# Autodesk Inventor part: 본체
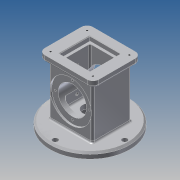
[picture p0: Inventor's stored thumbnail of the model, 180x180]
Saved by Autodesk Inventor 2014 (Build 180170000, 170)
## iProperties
Created: 2019-08
Part Number: 본체
Material: 알루미늄 6061
Document SubType Name: Modeling
Designer: kb542-14
Density: 2.71 g/cm^3
Appearance: 알루미늄 - 평지
Mass: 1040.33 g
Surface Area: 788.05 cm^2
Volume: 383.884 cm^3
Author: kb542-14
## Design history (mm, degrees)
sketch "스케치1"
  geometry: L1 (37, 33)-(-37, 33); L2 (-37, 33)-(-37, -33); L3 (-37, -33)-(37, -33); L4 (37, -33)-(37, 33); L5 (37, 33)-(-37, -33); L6 (-37, 33)-(37, -33); 1 further point
  constraints: 12 end point, 2 midpoint, 2 parallel, 1 horizontal, 1 perpendicular
  dimensions: "d1" = 74 distance of L1.start L1.end; "d2" = 66 distance of L1.end L2.end
extrude "돌출1" new body sketch "스케치1" distance "d3" = 88; taper "d4" = 0 deg
sketch "스케치2"
  geometry: L1 (46, 41)-(-46, 41); L2 (-46, 41)-(-46, -41); L3 (-46, -41)-(46, -41); L4 (46, -41)-(46, 41); L5 (46, 41)-(-46, -41); L6 (-46, 41)-(46, -41); 1 further point
  constraints: 12 end point, 2 midpoint, 2 parallel, 1 horizontal, 1 perpendicular
  dimensions: "d5" = 92 distance of L1.start L1.end; "d6" = 82 distance of L1.end L2.end
extrude "돌출2" join sketch "스케치2" distance "d7" = 10; taper "d8" = 0 deg
sketch "스케치3"
  geometry: C1 r 67.5 at (0, 0); 1 further point
  constraints: 1 centre point, 1 coincident
  dimensions: "d9" = 135 diameter of C1
extrude "돌출3" join sketch "스케치3" distance "d10" = 10; taper "d11" = 0 deg
sketch "스케치5"
  geometry: L1 (-33, 88)-(-41, 88) reference; L2 (-41, 88)-(-41, 98) reference; L3 (-41, 98)-(41, 98) reference; L4 (41, 98)-(41, 88) reference; L5 (41, 88)-(33, 88) reference; L6 (33, 88)-(33, 0) reference; L7 (33, 0)-(67.5, 0) reference; L8 (67.5, 0)-(67.5, -10) reference; L9 (67.5, -10)-(-67.5, -10) reference; L10 (-67.5, -10)-(-67.5, 0) reference; L11 (-67.5, 0)-(-33, 0) reference; L12 (-33, 0)-(-33, 88) reference; L13 (-33, 44)-(33, 44); L14 (-33, 79)-(-30, 79); L15 (-30, 79)-(-30, 68); L16 (-30, 68)-(30, 68); L17 (30, 68)-(30, 79); L18 (30, 79)-(33, 79); L19 (-33, 79)-(-33, 44); L20 (33, 79)-(33, 44); 1 further point
  constraints: 16 end point, 4 parallel, 2 collinear, 2 midpoint, 2 point on line, 1 perpendicular
  dimensions: "d18" = 70 diameter of L14 L13; "d20" = 48 diameter of L16 L13; "d21" = 70 diameter of L18 L13; "d22" = 3 distance of L14.start L14.end; "d23" = 3 distance of L17.end L18.end
revolve "회전2" sketch "스케치5" stored, may be unused: angle "d24" = 90 deg
sketch "스케치6"
  geometry: L1 (26, 26)-(-26, 26); L2 (-26, 26)-(-26, -26); L3 (-26, -26)-(26, -26); L4 (26, -26)-(26, 26); L5 (26, 26)-(-26, -26); L6 (-26, 26)-(26, -26); 1 further point
  constraints: 12 end point, 2 midpoint, 2 parallel, 1 horizontal, 1 perpendicular
  dimensions: "d25" = 52 distance of L1.end L2.end; "d26" = 52 distance of L1.start L1.end
extrude "돌출4" cut sketch "스케치6" distance "d27" = 8; taper "d28" = 0 deg
sketch "스케치7"
  geometry: L1 (22, 22)-(-22, 22); L2 (-22, 22)-(-22, -22); L3 (-22, -22)-(22, -22); L4 (22, -22)-(22, 22); L5 (22, 22)-(-22, -22); L6 (-22, 22)-(22, -22); 1 further point
  constraints: 12 end point, 2 midpoint, 2 parallel, 1 horizontal, 1 perpendicular
  dimensions: "d29" = 44 distance of L1.end L2.end; "d30" = 44 distance of L1.start L1.end
extrude "돌출5" cut sketch "스케치7" distance "d31" = 74; taper "d32" = 0 deg
sketch "스케치8"
  geometry: C1 r 67.5 at (0, 0) reference; C2 r 25 at (0, 0); C3 r 12.5 at (0, 0)
  constraints: 2 centre point, 2 coincident
  dimensions: "d34" = 50 diameter of C2; "d35" = 25 diameter of C3
extrude "돌출6" cut sketch "스케치8" distance "d36" = 50; taper "d37" = 0 deg
extrude "돌출7" cut sketch "스케치8" distance "d38" = 18; taper "d39" = 0 deg
sketch "스케치9"
  geometry: L1 (-88, 66)-(-88, 0) reference; L2 (-98, 100.5)-(-98, -34.5) reference; 5 further points
  constraints: 2 horizontal alignment, 2 midpoint
  dimensions: "d40" = 37 distance from line of L2 point (-61, 33); "d41" = 43 distance of point (-61, 33) point (-18, 33)
hole "구멍1" sketch "스케치9" at (-18, 33), (-61, 33) diameter "d42" = 4.917; stored, may be unused: countersink angle "d46" = 90 deg, drill point angle "d48" = 118 deg; dims "d43" = 6, "d44" = 4, "d45" = 2, "d47" = 22.75
fillet "모깎기1" dims "d49" = 3
fillet "모깎기2" dims "d50" = 3
fillet "모깎기3" dims "d51" = 3
fillet "모깎기4" dims "d52" = 10
fillet "모깎기6" dims "d54" = 3
fillet "모깎기7" dims "d55" = 3
fillet "모깎기8" dims "d56" = 3
chamfer "모따기1" distance "d57" = 3; stored, may be unused: second distance "d58" = 2, angle "d59" = 45 deg
fillet "모깎기9" dims "d60" = 3
sketch "스케치12"
  geometry: C1 r 64.5 at (0, 0) reference; C2 r 4.5 at (0, 59); C3 r 4.5 at (0, -59); C4 r 4.5 at (59, 0); A1 r 59 centre (0, 0) between (0, 59) and (0, -59)
  constraints: 4 centre point, 3 point on circle, 2 vertical alignment, 1 coincident, 1 horizontal alignment
  dimensions: "d61" = 118 diameter of A1; "d62" = 9 diameter of C2; "d63" = 9 diameter of C4; "d65" = 9 diameter of C3
extrude "돌출8" cut sketch "스케치12" stored distance "d66" = 18; taper "d67" = 0 deg
sketch "스케치13"
  geometry: A1 r 10 centre (36, -31) between (36, -41) and (46, -31) reference; A2 r 10 centre (36, 31) between (46, 31) and (36, 41) reference; A3 r 10 centre (-36, 31) between (-36, 41) and (-46, 31) reference; A4 r 10 centre (-36, -31) between (-46, -31) and (-36, -41) reference; 5 further points
  constraints: 4 coincident
hole "구멍2" sketch "스케치13" at (-36, 31), (-36, -31), (36, -31), (36, 31) diameter "d68" = 3.242; stored, may be unused: countersink angle "d72" = 90 deg, drill point angle "d74" = 118 deg; dims "d69" = 4, "d70" = 4, "d71" = 2, "d73" = 6
sketch "스케치14" dims "d75" = 58
  geometry: C1 r 24 at (0, 0) reference; C2 r 35 at (0, 0) reference; 3 further points
  constraints: 2 vertical alignment, 1 coincident, 2 other
hole "구멍3" sketch "스케치14" at (0, -29) diameter "d76" = 3.242; stored, may be unused: countersink angle "d80" = 90 deg, drill point angle "d82" = 118 deg; dims "d77" = 4, "d78" = 4, "d79" = 2, "d81" = 6
sketch "스케치15"
  geometry: L1 (-34, -36)-(34, -36) reference; L2 (0, 0)-(-64.5, 0); 2 further points
  constraints: 2 coincident, 2 end point, 1 horizontal alignment, 1 parallel, 1 other
chamfer "모따기2" distance "d86" = 1; stored, may be unused: second distance "d87" = 2, angle "d88" = 45 deg
fillet "모깎기10" dims "d89" = 3
feature "엠보싱1" dims "d1" = 74, "d2" = 66, "d90" = 0.5, "d91" = 0
node "솔리드1"
pattern_circular "원형 패턴1" dims angle "d84" = 360 deg
mirror "대칭1"
node "절단 모서리 투영2"
